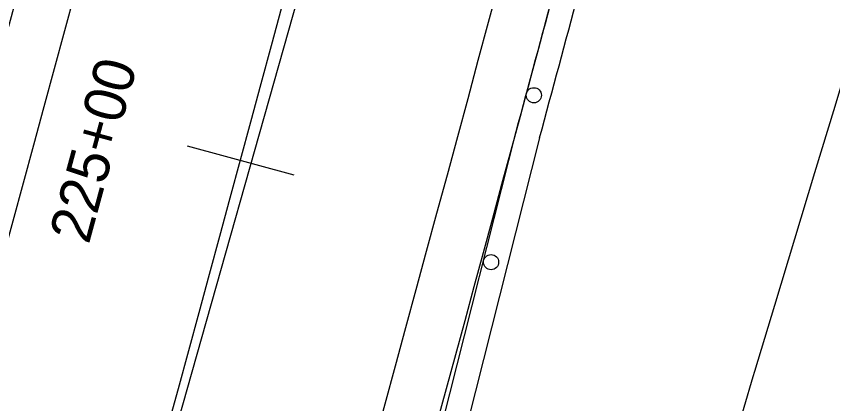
# Model space of a CAD drawing. Extents: x 1441466 to 1476381, y 2042742 to 2057194.
# Drawn here: x 1446049 to 1446167.4, y 2055386.4 to 2055442.6 of the extents above; entities that cross this region are included whole.
import ezdxf

# ---------------------------------------------------------------- set-up
doc = ezdxf.new("R2010")
doc.units = 0
for name, color, linetype in [('R_Guardrail', 7, 'Continuous'), ('R_Horz Alg', 7, 'Continuous'), ('R_Horz Alg Annot', 7, 'Continuous'), ('R_Horz Alg Stationing', 7, 'Continuous'), ('R_Proposed Const Limits', 7, 'Continuous'), ('R_Proposed Road', 7, 'Continuous'), ('R_Shld', 7, 'Continuous')]:
    doc.layers.add(name, color=color, linetype=linetype)

msp = doc.modelspace()

# ---------------------------------------------------------------- linework, layer by layer
at = {"layer": 'R_Guardrail'}
msp.add_line((1446078.48, 2055255.86), (1446121.49, 2055425.89), dxfattribs=at)
for centre in [(1446124.05, 2055431.16), (1446117.84, 2055406.97)]:
    msp.add_circle(centre, 1.1, dxfattribs=at)
msp.add_arc((1423960.29, 2061413.42), 22955.81, 344.88077, 344.988714, dxfattribs=at)
at = {"layer": 'R_Horz Alg'}
msp.add_arc((1423960.81, 2061415.35), 22918.31, 344.166667, 346, dxfattribs=at)
at = {"layer": 'R_Horz Alg Annot'}
msp.add_line((1446109.63, 2055515.11), (1446055.76, 2055325.15), dxfattribs=at)
at = {"layer": 'R_Horz Alg Stationing'}
msp.add_lwpolyline([(1446073.79, 2055423.83), (1446089.23, 2055419.65)], dxfattribs=at)
at = {"layer": 'R_Proposed Const Limits'}
msp.add_lwpolyline([(1446153.22, 2055381.52), (1446155.86, 2055390.41), (1446156.08, 2055391.14), (1446159, 2055400.75), (1446161.9, 2055410.36), (1446164.79, 2055419.97), (1446167.7, 2055429.58), (1446170.39, 2055438.46), (1446170.59, 2055439.2), (1446170.77, 2055447.39)], dxfattribs=at)
at = {"layer": 'R_Proposed Road'}
for radius, end in [(22888.81, 346), (22947.81, 346), (22880.81, 344.983157), (22955.81, 344.983722)]:
    msp.add_arc((1423960.81, 2061415.35), radius, 344.166667, end, dxfattribs=at)
at = {"layer": 'R_Shld'}
msp.add_line((1446124.87, 2055425), (1446081.87, 2055255), dxfattribs=at)
msp.add_arc((1423960.29, 2061413.42), 22959.31, 344.88084, 344.988739, dxfattribs=at)

# ---------------------------------------------------------------- texts
at = {"layer": 'R_Horz Alg Stationing'}
msp.add_text('225+00', height=6, rotation=74.8397, dxfattribs=at).set_placement((1446059.52, 2055409.42))

doc.saveas('drawing.dxf')
